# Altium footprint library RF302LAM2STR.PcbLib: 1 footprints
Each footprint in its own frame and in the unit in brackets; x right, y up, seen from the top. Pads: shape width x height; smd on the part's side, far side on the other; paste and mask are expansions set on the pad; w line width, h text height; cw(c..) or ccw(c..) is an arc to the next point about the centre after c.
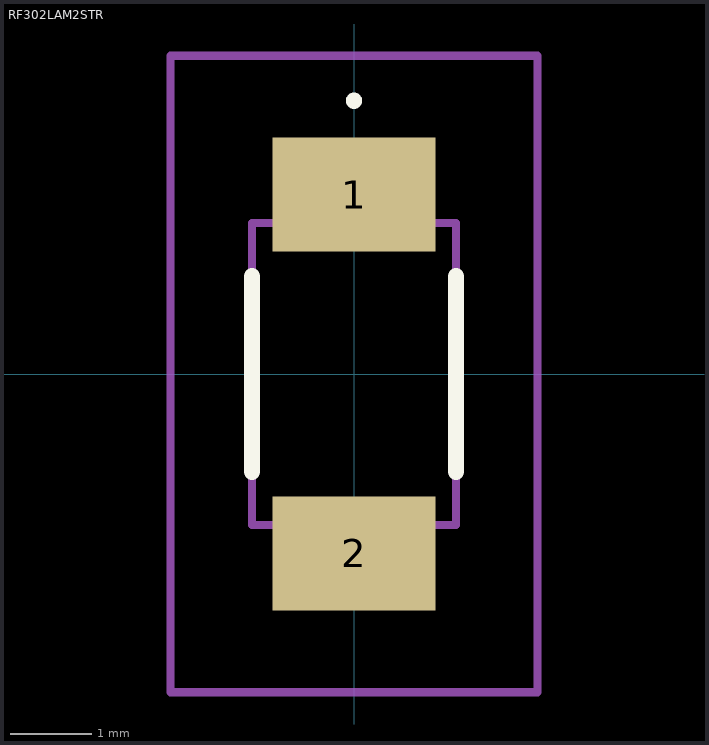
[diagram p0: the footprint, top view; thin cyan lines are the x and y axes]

## RF302LAM2STR [mm]
pads (2):
  rect 2x1.4 smd: 1(0,2.2) 2(0,-2.2)
Top Overlay:
  lines w0.1: 0,3.3 cw(c0,3.35) 0,3.4 ; 0,3.3 0,3.3 ; 0,3.3 ccw(c0,3.35) 0,3.4 ; 0,3.4 0,3.4
  lines w0.2: -1.25,-1.2 -1.25,1.2 ; 1.25,-1.2 1.25,1.2
Mechanical 15:
  lines w0.1: -1.25,-1.85 1.25,-1.85 1.25,1.85 -1.25,1.85 -1.25,-1.85
Mechanical 20:
  lines w0.1: -2.25,-3.9 2.25,-3.9 2.25,3.9 -2.25,3.9 -2.25,-3.9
